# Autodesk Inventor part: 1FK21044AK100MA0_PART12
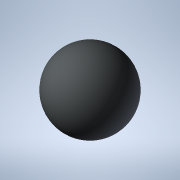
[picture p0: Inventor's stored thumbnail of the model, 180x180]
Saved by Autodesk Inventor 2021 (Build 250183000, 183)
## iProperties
Created: 2025-04
Part Number: 1FK21044AK100MA0_PART12
Material: Generic
Catalog Web Link: www.3dfindit.com
Description: -Servo synchronous motor
Document SubType Name: Modeling
Designer: psAdmin
Mass: 0.137258 g
Surface Area: 1.2868 cm^2
Volume: 0.137258 cm^3
Density: 1 g/cm^3
Appearance: PSOLRGB-212-217-219
Category: PARTsolutions
Title: 1FK21044AK100MA0_PART12
Author: Cadenas PARTsolutions
Comments: Servo synchronous motor
Sending System: PARTsolutions
Preprocessor: ST-DEVELOPER v19.3
PSOL_IDENT_0: {$CADENAS_DATA/23d-libs/siemens_ag/_cat_/5e/d8/1fk21044ak100ma0.prj},216 {VTYP=3D},{NB=1FK21044AK100
PSOL_IDENT_1: MA0_PART12},{LINA=1FK21044AK100MA0_PART12},{NN=1FK21044AK100MA0_PART12},{NOPRJ=TRUE},{DATE=19.08.202
PSOL_IDENT_2: 5 14:00:41},{GEOMDATE=30.07.2025 02:00:53},{VERSION=},{LINEID=10},{WBVAR=},{WBNUMERIC=}  {NB=1FK2104
PSOL_IDENT_3: 4AK100MA0_PART12},{LINA=1FK21044AK100MA0_PART12},{KT=DUMMY},{PREVIEW=../../../_pool_/cb/72/p_d211_xx
PSOL_IDENT_4: _00434j.png},{DESCSHORT=SIMOTICS S-1FK2 HD, SINAMICS S210 3AC 400V-480V, 0.95 Nm, 6000 rpm},{DESCLON
PSOL_IDENT_5: G=SIMOTICS S-1FK2 HD servo motor M0=1.27 Nm; PN = 0.6 kW at nN=6000 rpm (380-480 V); PN = 0.4 kW at
PSOL_IDENT_6: nN=3000 rpm (200-240 V); with holding brake; degree of protection IP64; cylindrical shaft D19x40mm;
PSOL_IDENT_7: absolute encoder 22-bit + 12-bit multiturn (encoder AM22DQC); with OCC interface; plug size M17, rot
PSOL_IDENT_8: atable; SIMOTICS S-1FK2 servomotorfor a wide range of uses in industrial environments. SIMOTICS S‑1F
PSOL_IDENT_9: K2 servomotors are compact synchronous motors with a high dynamic performance that set themselves ap
PSOL_IDENT_10: art as a result of their high power density, degree of protection and overload capability. The motor
PSOL_IDENT_11: s are available in two variants: as High Dynamic variant (highest dynamic performance as a result of
PSOL_IDENT_12: the low intrinsic moment of inertia for applications demanding a high dynamic performance with low
PSOL_IDENT_13: moved masses) - and as Compact variant (precise and stable closed-loop control for medium up to larg
PSOL_IDENT_14: e moved masses as a result of a medium intrinsic moment of inertia). SIMOTICSS‑1FK2 servomotors full
PSOL_IDENT_15: y exploit their strengths in a system with the SINAMICSS210 frequency converter and simple connectio
PSOL_IDENT_16: n using the one cable connection (OCC). Advantages include the short control and positioning times,
PSOL_IDENT_17: fast and precise correction of disturbing quantities as well as stable control with a high dynamic p
PSOL_IDENT_18: erformance. The servo motors can be configured to address a wide range of requirements. For example
PSOL_IDENT_19: with and without holding brake, IP64 or IP65 degree of protection, singleturn or multiturn absolute
PSOL_IDENT_20: encoders - to name just a few. Further, the servomotors are available in different shaft heights ext
PSOL_IDENT_21: ending from 20 to 100. A shaft sealing ring is available to achieve an IP65 degree of protection and
PSOL_IDENT_22: for subsequent mounting at the motor or as spare part. SIMOTICS - the optimum motor for each and ev
PSOL_IDENT_23: ery motion control application.},{INTNO=804766910005},{SUPPLIERALTNO=1FK2104-4AK10-0MA0},{MANUID=1FK
PSOL_IDENT_24: 21044AK100MA0},{MANUNAME=Siemens},{MANUTYPEDESC=Synchronous motor 1FK2-HD 1,27 Nm},{AAU732=SIMOTICS}
PSOL_IDENT_25: ,{AAO057=S-1FK2},{AAU734=SIMOTICS S-1FK2 HD servo motor M0=1.27 Nm; PN = 0.6 kW at nN=6000 rpm (380-
PSOL_IDENT_26: 480 V); PN = 0.4 kW at nN=3000 rpm (200-240 V); with holding brake; degree of protection IP64; cylin
PSOL_IDENT_27: drical shaft D19x40mm; absolute encoder 22-bit + 12-bit multiturn (encoder AM22DQC); with OCC interf
PSOL_IDENT_28: ace; plug size M17, rotatable;},{AAW338=Synchronous motor 1FK2-HD 1,27 Nm},{AAO742=SIMOTICS},{AAO663=
PSOL_IDENT_29: 4042948691076},{NOCUPEROU=1},{PRICEQUANTITY=1},{QUANTITYMIN=1},{QUANTITYINT=1},{CTN=85015100},{COO=D
PSOL_IDENT_30: E},{AAO676=1FK2104-4AK10-0MA0},{AAO677=Siemens AG},{ORDERUNIT=C62},{CONTENTUNIT=C62}
NB: 1FK21044AK100MA0_PART12
NT: Servo synchronous motor
NBSYN: $MANUID._PART12
LINA: 1FK21044AK100MA0_PART12
CATALOG: SIEMENS
PREVIEW: ../../../_pool_/cb/72/p_d211_xx_00434j.png
DESCSHORT: SIMOTICS S-1FK2 HD, SINAMICS S210 3AC 400V-480V, 0.95 Nm, 6000 rpm
DESCLONG: SIMOTICS S-1FK2 HD servo motor M0=1.27 Nm; PN = 0.6 kW at nN=6000 rpm (380-480 V); PN = 0.4 kW at nN=3000 rpm (200-240 V); with holding brake; degree of protect
INTNO: 804766910005
SUPPLIERALTNO: 1FK2104-4AK10-0MA0
MANUID: 1FK21044AK100MA0
MANUNAME: Siemens
MANUTYPEDESC: Synchronous motor 1FK2-HD 1,27 Nm
AAU732: SIMOTICS
AAO057: S-1FK2
AAU734: SIMOTICS S-1FK2 HD servo motor M0=1.27 Nm; PN = 0.6 kW at nN=6000 rpm (380-480 V); PN = 0.4 kW at nN=3000 rpm (200-240 V); with holding brake; degree of protect
AAW338: Synchronous motor 1FK2-HD 1,27 Nm
AAO742: SIMOTICS
AAO663: 4042948691076.0
NOCUPEROU: 1
PRICEQUANTITY: 1
QUANTITYMIN: 1
QUANTITYINT: 1
CTN: 85015100
COO: DE
ARTICLENO: 1FK21044AK100MA0_PART12
BOMINFO: 1FK21044AK100MA0_PART12
CREATOR: CADENAS GmbH
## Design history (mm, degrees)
feature "2025_04_17_15_35_41_0968"
body "Solid1"
